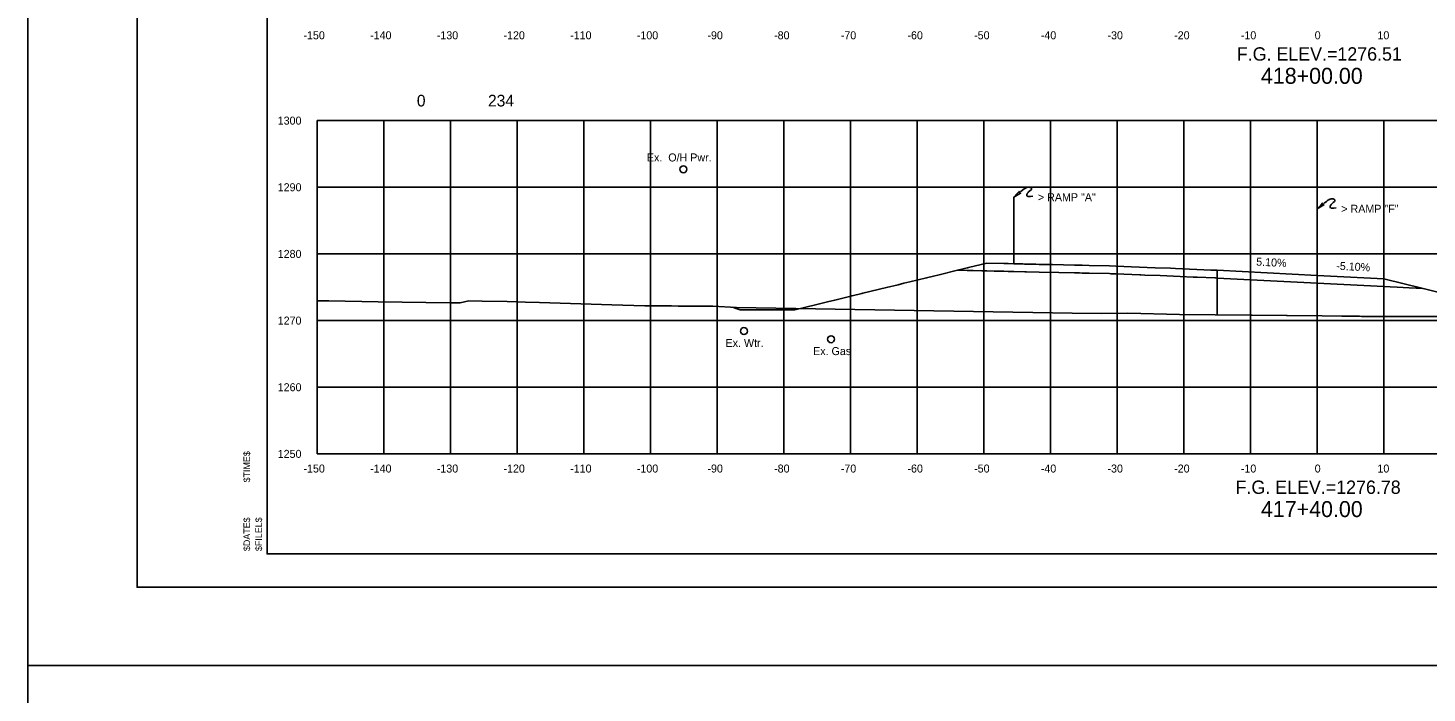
# Model space of a CAD drawing. Extents: x 2148105 to 2149976, y 144169 to 149705.
# Drawn here: x 2148219.9 to 2148429.8, y 148741 to 148840.8 of the extents above; entities that cross this region are included whole.
import ezdxf

# ---------------------------------------------------------------- set-up
doc = ezdxf.new("R2010")
doc.units = 0
for name, color, linetype in [('Bridge M-Header', 7, 'Continuous'), ('Default', 7, 'Continuous'), ('INR_Tracking', 7, 'Continuous'), ('PH1a-PR-Drives', 7, 'Continuous'), ('PH1a-PR-ServRd', 7, 'Continuous'), ('PH2-PR-Barrier', 7, 'Continuous'), ('PR-AttenuatorPad', 7, 'Continuous'), ('PR_Align_PC', 7, 'Continuous'), ('PR_Align_Ramp_E', 7, 'Continuous'), ('PR_Align_Ramp_J', 7, 'Continuous'), ('PR_Storm_Channel', 7, 'Continuous'), ('PR_Storm_Conc_Box_PH1B', 7, 'Continuous'), ('PR_Storm_Conc_Pipe', 7, 'Continuous'), ('PR_Storm_Conc_Pipe_PH1B', 7, 'Continuous'), ('PR_Storm_Inlet_CICI_PH1B', 7, 'Continuous'), ('PR_Storm_Junction_Box_PH1A', 7, 'Continuous'), ('PR_Storm_Junction_Box_PH1B', 7, 'Continuous'), ('PR_Storm_MH_PH1B', 7, 'Continuous'), ('PR_Storm_Standard_Median_Drain_PH1B', 7, 'Continuous'), ('PR_Storm_Txt_PH1B', 7, 'Continuous'), ('TopCut', 7, 'Continuous')]:
    doc.layers.add(name, color=color, linetype=linetype)

# ---------------------------------------------------------------- blocks, each defined once
blk = doc.blocks.new('POINT_DISPLAY')
at = {"layer": 'Default'}
blk.add_line((0, 0), (0, 0), dxfattribs=at)

msp = doc.modelspace()

# ---------------------------------------------------------------- linework, layer by layer
at = {"layer": 'INR_Tracking'}
msp.add_lwpolyline([(2148398.32, 148803.28), (2148399.29, 148803.23), (2148413.32, 148802.52), (2148413.32, 148802.52), (2148415.32, 148802.42), (2148423.32, 148802.01), (2148424.26, 148801.96), (2148425.31, 148801.91), (2148425.32, 148801.91), (2148427.08, 148801.82), (2148429.19, 148801.71), (2148429.19, 148801.71), (2148432.62, 148800.85), (2148435.31, 148800.18), (2148435.32, 148800.18), (2148443.32, 148800.18), (2148443.32, 148800.18), (2148458.95, 148803.64), (2148498.33, 148812.39)], dxfattribs=at)
at = {"layer": 'PH1a-PR-ServRd'}
msp.add_lwpolyline([(2148570.82, 148761.91), (2148255.82, 148761.91), (2148255.82, 148971.91), (2148570.82, 148971.91)], close=True, dxfattribs=at)
at = {"layer": 'PH2-PR-Barrier'}
msp.add_line((2148413.32, 148803.69), (2148413.32, 148813.69), dxfattribs=at)
for points in [[(2148413.32, 148813.69), (2148413.84, 148814.24), (2148414.1, 148814.54), (2148414.18, 148814.38), (2148414.32, 148814.26), (2148413.32, 148813.69)], [(2148414.33, 148814.5), (2148414.69, 148814.79), (2148414.85, 148814.92), (2148414.94, 148814.99), (2148415.04, 148815.05), (2148415.14, 148815.09), (2148415.26, 148815.13), (2148415.39, 148815.16), (2148415.49, 148815.17), (2148415.57, 148815.17), (2148415.65, 148815.16), (2148415.72, 148815.15), (2148415.78, 148815.14), (2148415.83, 148815.12), (2148415.87, 148815.09), (2148415.91, 148815.06), (2148415.95, 148815.01), (2148415.98, 148814.96), (2148415.97, 148814.9), (2148415.96, 148814.86), (2148415.91, 148814.79), (2148415.72, 148814.63), (2148415.53, 148814.47), (2148415.46, 148814.39), (2148415.39, 148814.32), (2148415.33, 148814.22), (2148415.29, 148814.16), (2148415.25, 148814.07), (2148415.25, 148813.99), (2148415.27, 148813.91), (2148415.31, 148813.84), (2148415.36, 148813.81), (2148415.42, 148813.78), (2148415.53, 148813.77), (2148415.66, 148813.77), (2148415.82, 148813.79), (2148416.15, 148813.83)]]:
    msp.add_lwpolyline(points, dxfattribs=at)
at = {"layer": 'PR-AttenuatorPad'}
msp.add_line((2148367.82, 148805.43), (2148367.82, 148815.43), dxfattribs=at)
for points in [[(2148367.82, 148815.43), (2148368.33, 148815.98), (2148368.6, 148816.29), (2148368.68, 148816.12), (2148368.82, 148816), (2148367.82, 148815.43)], [(2148368.83, 148816.24), (2148369.18, 148816.53), (2148369.34, 148816.66), (2148369.44, 148816.73), (2148369.54, 148816.79), (2148369.64, 148816.84), (2148369.75, 148816.87), (2148369.89, 148816.9), (2148369.98, 148816.91), (2148370.07, 148816.91), (2148370.15, 148816.91), (2148370.22, 148816.89), (2148370.27, 148816.88), (2148370.33, 148816.86), (2148370.37, 148816.83), (2148370.41, 148816.8), (2148370.44, 148816.76), (2148370.47, 148816.7), (2148370.47, 148816.64), (2148370.46, 148816.6), (2148370.4, 148816.53), (2148370.22, 148816.37), (2148370.03, 148816.21), (2148369.95, 148816.13), (2148369.89, 148816.06), (2148369.83, 148815.96), (2148369.79, 148815.9), (2148369.75, 148815.81), (2148369.74, 148815.74), (2148369.77, 148815.65), (2148369.81, 148815.58), (2148369.86, 148815.55), (2148369.91, 148815.52), (2148370.02, 148815.51), (2148370.16, 148815.52), (2148370.31, 148815.53), (2148370.65, 148815.57)]]:
    msp.add_lwpolyline(points, dxfattribs=at)
at = {"layer": 'PR_Align_Ramp_E'}
for points in [[(2148219.95, 148985.16), (2148579.95, 148985.16), (2148579.95, 148745.16), (2148219.95, 148745.16)], [(2148219.95, 148745.16), (2148579.95, 148745.16), (2148579.95, 148505.16), (2148219.95, 148505.16)]]:
    msp.add_lwpolyline(points, close=True, dxfattribs=at)
at = {"layer": 'PR_Align_Ramp_J'}
msp.add_lwpolyline([(2148236.32, 148976.91), (2148576.32, 148976.91), (2148576.32, 148756.91), (2148236.32, 148756.91)], close=True, dxfattribs=at)
at = {"layer": 'PR_Storm_Channel'}
msp.add_lwpolyline([(2148398.32, 148804.45), (2148413.32, 148803.69), (2148415.32, 148803.58), (2148423.32, 148803.18), (2148429.19, 148801.71)], dxfattribs=at)
at = {"layer": 'PR_Storm_Conc_Box_PH1B'}
for p, q in [((2148263.32, 148826.91), (2148563.32, 148826.91)), ((2148263.32, 148776.91), (2148263.32, 148826.91)), ((2148273.32, 148776.91), (2148273.32, 148826.91)), ((2148283.32, 148776.91), (2148283.32, 148826.91)), ((2148293.32, 148776.91), (2148293.32, 148826.91)), ((2148303.32, 148776.91), (2148303.32, 148826.91)), ((2148313.32, 148776.91), (2148313.32, 148826.91)), ((2148323.32, 148776.91), (2148323.32, 148826.91)), ((2148333.32, 148776.91), (2148333.32, 148826.91)), ((2148343.32, 148776.91), (2148343.32, 148826.91)), ((2148353.32, 148776.91), (2148353.32, 148826.91)), ((2148363.32, 148776.91), (2148363.32, 148826.91)), ((2148373.32, 148776.91), (2148373.32, 148826.91)), ((2148383.32, 148776.91), (2148383.32, 148826.91)), ((2148393.32, 148776.91), (2148393.32, 148826.91)), ((2148403.32, 148776.91), (2148403.32, 148826.91)), ((2148413.32, 148776.91), (2148413.32, 148826.91)), ((2148423.32, 148776.91), (2148423.32, 148826.91)), ((2148263.32, 148816.91), (2148563.32, 148816.91)), ((2148263.32, 148806.91), (2148563.32, 148806.91)), ((2148263.32, 148796.91), (2148563.32, 148796.91)), ((2148263.32, 148786.91), (2148563.32, 148786.91)), ((2148263.32, 148776.91), (2148563.32, 148776.91))]:
    msp.add_line(p, q, dxfattribs=at)
at = {"layer": 'PR_Storm_Conc_Pipe'}
for points in [[(2148325.62, 148798.9), (2148326.33, 148798.67), (2148326.75, 148798.53), (2148328.23, 148798.52), (2148329.3, 148798.52), (2148330.18, 148798.52), (2148330.85, 148798.52), (2148332.49, 148798.52), (2148334.59, 148798.52), (2148334.62, 148798.52), (2148334.95, 148798.52), (2148334.95, 148798.52), (2148334.96, 148798.52), (2148338.07, 148799.28), (2148339.88, 148799.72), (2148340.95, 148799.98), (2148343.38, 148800.57), (2148343.53, 148800.6), (2148343.57, 148800.61), (2148345, 148800.96), (2148345.17, 148801), (2148348.69, 148801.86), (2148350.45, 148802.29), (2148351.33, 148802.5), (2148352.19, 148802.71), (2148354.71, 148803.32), (2148355.74, 148803.57), (2148356.61, 148803.78), (2148359.35, 148804.45), (2148360.81, 148804.42), (2148360.89, 148804.41), (2148361.03, 148804.41), (2148361.72, 148804.4), (2148362.99, 148804.37), (2148363.74, 148804.35), (2148364.86, 148804.33), (2148366.31, 148804.3), (2148366.97, 148804.28), (2148367.82, 148804.26), (2148369.44, 148804.23), (2148369.7, 148804.22), (2148371.6, 148804.18), (2148374.56, 148804.11), (2148376.89, 148804.06), (2148377.64, 148804.05), (2148378.06, 148804.04), (2148379.13, 148804.01), (2148382.18, 148803.95), (2148382.38, 148803.94), (2148383.09, 148803.93), (2148386.68, 148803.77), (2148386.87, 148803.77), (2148387.46, 148803.74), (2148389.74, 148803.65), (2148392.75, 148803.52), (2148394.68, 148803.44), (2148395.3, 148803.41), (2148397.97, 148803.3), (2148398.04, 148803.3), (2148398.32, 148803.28)], [(2148398.32, 148803.28), (2148398.32, 148803.62), (2148398.32, 148804.45)]]:
    msp.add_lwpolyline(points, dxfattribs=at)
at = {"layer": 'PR_Storm_Conc_Pipe_PH1B'}
msp.add_lwpolyline([(2148255.82, 148761.91), (2148570.82, 148761.91), (2148570.82, 148971.91), (2148255.82, 148971.91)], close=True, dxfattribs=at)
msp.add_lwpolyline([(2148255.82, 148761.91), (2148570.82, 148761.91), (2148570.82, 148971.91), (2148255.82, 148971.91)], close=True, dxfattribs=at)
at = {"layer": 'PR_Storm_Inlet_CICI_PH1B'}
msp.add_lwpolyline([(2148263.32, 148799.88), (2148265.09, 148799.86), (2148272.49, 148799.73), (2148283.22, 148799.59), (2148283.97, 148799.58), (2148284.7, 148799.58), (2148284.75, 148799.58), (2148286.09, 148799.85), (2148288.05, 148799.82), (2148291.82, 148799.78), (2148294.56, 148799.69), (2148296.65, 148799.6), (2148307.53, 148799.28), (2148312.48, 148799.13), (2148313.39, 148799.11), (2148315.94, 148799.1), (2148316.47, 148799.1), (2148317.46, 148799.09), (2148321.47, 148799.06), (2148322.66, 148799.05), (2148326.19, 148798.87), (2148376.55, 148798.03), (2148381.01, 148797.96), (2148384.9, 148798.04), (2148392.65, 148797.81), (2148414.05, 148797.6), (2148425.26, 148797.52), (2148444.49, 148797.55)], dxfattribs=at)
at = {"layer": 'PR_Storm_Junction_Box_PH1A'}
for centre in [(2148318.25, 148819.6), (2148327.33, 148795.33), (2148340.4, 148794.11)]:
    msp.add_circle(centre, 0.516, dxfattribs=at)
at = {"layer": 'PR_Storm_Standard_Median_Drain_PH1B'}
for q in [(2148263.32, 148826.91), (2148563.32, 148776.91)]:
    msp.add_line((2148263.32, 148776.91), q, dxfattribs=at)
at = {"layer": 'PR_Storm_Txt_PH1B'}
msp.add_lwpolyline([(2148359.35, 148804.45), (2148360.03, 148804.61), (2148360.82, 148804.81), (2148360.95, 148804.84), (2148361.03, 148804.86), (2148363.74, 148805.52), (2148366.32, 148805.46), (2148366.97, 148805.45), (2148367.82, 148805.43), (2148369.16, 148805.4), (2148369.43, 148805.39), (2148371.13, 148805.36), (2148371.6, 148805.34), (2148373.6, 148805.3), (2148376.89, 148805.23), (2148377.33, 148805.22), (2148378.06, 148805.2), (2148379.13, 148805.18), (2148382.18, 148805.11), (2148383.09, 148805.09), (2148389, 148804.84), (2148391.28, 148804.75), (2148392.03, 148804.72), (2148397.37, 148804.49), (2148397.88, 148804.47), (2148398.32, 148804.45)], dxfattribs=at)
at = {"layer": 'TopCut'}
msp.add_lwpolyline([(2148432.62, 148800.85), (2148429.19, 148801.71), (2148429.19, 148801.71), (2148427.08, 148801.82), (2148425.32, 148801.91), (2148425.31, 148801.91), (2148424.26, 148801.96), (2148423.32, 148802.01), (2148415.32, 148802.42), (2148413.32, 148802.52), (2148413.32, 148802.52), (2148399.29, 148803.23), (2148398.32, 148803.28), (2148398.32, 148797.75), (2148414.05, 148797.6), (2148419.96, 148797.54), (2148420.12, 148797.54), (2148420.17, 148797.54), (2148420.29, 148797.54), (2148420.48, 148797.54), (2148420.68, 148797.54), (2148420.9, 148797.54), (2148421.14, 148797.54), (2148421.4, 148797.54), (2148421.7, 148797.54), (2148421.99, 148797.54), (2148422.02, 148797.54), (2148422.37, 148797.54), (2148422.77, 148797.54), (2148423.22, 148797.53), (2148423.73, 148797.53), (2148424.33, 148797.53), (2148425.02, 148797.52), (2148425.26, 148797.52), (2148425.85, 148797.52), (2148426.36, 148797.52), (2148426.86, 148797.52), (2148428.08, 148797.52), (2148429.61, 148797.53), (2148431.56, 148797.53)], dxfattribs=at)

# ---------------------------------------------------------------- block references
at = {"layer": 'PR_Storm_Conc_Pipe_PH1B', "xscale": 10, "yscale": 10}
for p in [(2148398.32, 148804.45), (2148398.32, 148804.45), (2148415.32, 148803.58), (2148415.32, 148803.58), (2148423.32, 148803.18), (2148423.32, 148803.18)]:
    msp.add_blockref('POINT_DISPLAY', p, dxfattribs=at)

# ---------------------------------------------------------------- texts
at = {"layer": 'Bridge M-Header'}
for s, p in [('5.10%', (2148404.13, 148805.16)), ('-5.10%', (2148416.14, 148804.54))]:
    msp.add_text(s, height=1.2, rotation=357.0804, dxfattribs=at).set_placement(p)
at = {"layer": 'PH1a-PR-Drives'}
for s, p in [('$TIME$', (2148253.27, 148772.63)), ('$DATE$', (2148253.27, 148762.33)), ('$FILEL$', (2148255.05, 148762.33))]:
    msp.add_text(s, height=1, rotation=90, dxfattribs=at).set_placement(p)
at = {"layer": 'PH2-PR-Barrier'}
msp.add_text('> RAMP "F"', height=1.2, rotation=360, dxfattribs=at).set_placement((2148416.92, 148813.08))
at = {"layer": 'PR-AttenuatorPad'}
msp.add_text('> RAMP "A"', height=1.2, rotation=360, dxfattribs=at).set_placement((2148371.42, 148814.82))
at = {"layer": 'PR_Align_PC'}
for s, p in [('0', (2148278.27, 148829.03)), ('234', (2148288.94, 148829.03))]:
    msp.add_text(s, height=1.75, dxfattribs=at).set_placement(p)
at = {"layer": 'PR_Storm_Junction_Box_PH1A'}
for s, p in [('Ex.  O/H Pwr.', (2148312.77, 148820.78)), ('Ex. Wtr.', (2148324.57, 148792.95)), ('Ex. Gas', (2148337.7, 148791.73))]:
    msp.add_text(s, height=1.2, rotation=360, dxfattribs=at).set_placement(p)
at = {"layer": 'PR_Storm_Junction_Box_PH1B'}
for s, p in [('418+00.00', (2148404.87, 148832.43)), ('417+40.00', (2148404.87, 148767.43))]:
    msp.add_text(s, height=2.4, dxfattribs=at).set_placement(p)
at = {"layer": 'PR_Storm_MH_PH1B'}
for s, height, p in [('-150', 1.2, (2148261.26, 148839.11)), ('-140', 1.2, (2148271.26, 148839.11)), ('-130', 1.2, (2148281.26, 148839.11)), ('-120', 1.2, (2148291.26, 148839.11)), ('-110', 1.2, (2148301.26, 148839.11)), ('-100', 1.2, (2148311.26, 148839.11)), ('-90', 1.2, (2148321.85, 148839.11)), ('-80', 1.2, (2148331.85, 148839.11)), ('-70', 1.2, (2148341.85, 148839.11)), ('-60', 1.2, (2148351.85, 148839.11)), ('-50', 1.2, (2148361.85, 148839.11)), ('-40', 1.2, (2148371.85, 148839.11)), ('-30', 1.2, (2148381.85, 148839.11)), ('-20', 1.2, (2148391.85, 148839.11)), ('-10', 1.2, (2148401.85, 148839.11)), ('0', 1.2, (2148412.93, 148839.11)), ('10', 1.2, (2148422.34, 148839.11)), ('F.G. ELEV.=1276.51', 2, (2148401.25, 148835.91)), ('1300', 1.2, (2148257.4, 148826.31)), ('1290', 1.2, (2148257.4, 148816.31)), ('1280', 1.2, (2148257.4, 148806.31)), ('1270', 1.2, (2148257.4, 148796.31)), ('1260', 1.2, (2148257.4, 148786.31)), ('1250', 1.2, (2148257.4, 148776.31)), ('-150', 1.2, (2148261.26, 148774.11)), ('-140', 1.2, (2148271.26, 148774.11)), ('-130', 1.2, (2148281.26, 148774.11)), ('-120', 1.2, (2148291.26, 148774.11)), ('-110', 1.2, (2148301.26, 148774.11)), ('-100', 1.2, (2148311.26, 148774.11)), ('-90', 1.2, (2148321.85, 148774.11)), ('-80', 1.2, (2148331.85, 148774.11)), ('-70', 1.2, (2148341.85, 148774.11)), ('-60', 1.2, (2148351.85, 148774.11)), ('-50', 1.2, (2148361.85, 148774.11)), ('-40', 1.2, (2148371.85, 148774.11)), ('-30', 1.2, (2148381.85, 148774.11)), ('-20', 1.2, (2148391.85, 148774.11)), ('-10', 1.2, (2148401.85, 148774.11)), ('0', 1.2, (2148412.93, 148774.11)), ('10', 1.2, (2148422.34, 148774.11)), ('F.G. ELEV.=1276.78', 2, (2148401.07, 148770.91))]:
    msp.add_text(s, height=height, dxfattribs=at).set_placement(p)

doc.saveas('drawing.dxf')
